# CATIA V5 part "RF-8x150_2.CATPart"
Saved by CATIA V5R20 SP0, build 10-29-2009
Part number: _RF-8x150/2
Definition: NONE
Nomenclature: _RF-8x150/2
Source: Unknown
Description: PART-_RF-8x150/2-DESC
Bounding box of the stored display mesh (mm): x -150 to 18, y -4.9 to 4.9, z -4.9 to 4.9
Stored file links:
  C:\Users\Utente\Desktop\IO LAVORO\3D X SITO CF\X SITO\PLASTICA\RF\RF-8x150_2.CATPart
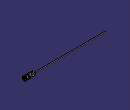
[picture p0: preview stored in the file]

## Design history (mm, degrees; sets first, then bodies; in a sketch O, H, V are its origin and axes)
Body1 "_RF-8x150/2" (main body)
  Solid1: solid without history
